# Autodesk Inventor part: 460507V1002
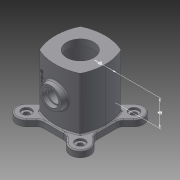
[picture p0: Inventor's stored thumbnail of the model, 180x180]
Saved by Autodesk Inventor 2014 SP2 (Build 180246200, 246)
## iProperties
Created: 2016-05
Part Number: 460507V1002
Material: Generic
Document SubType Name: Modeling
Designer: 달님반
Density: 1 g/cm^3
Appearance: Default
Author: 달님반
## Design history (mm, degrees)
sketch "스케치1"
  geometry: L1 (46, 0)-(46, -0.095); L2 (46, -46)-(-46, -46); L3 (-0.047, -0.047)-(66.486, -66.58); L4 (66.486, -66.58)-(-51.682, 51.587); L5 (-46, -46)-(46, 46); L6 (-46, -26.455)-(-46, 0); L7 (-46, 45.905)-(-46, 46); L8 (-0.095, 46)-(0, 46); A1 r 53 centre (-0.047, -0.047) between (-46, -26.455) and (-37.524, -37.524); A2 r 87.09 centre (41.09, -0.047) between (-37.524, 37.429) and (-37.524, -37.524); A3 r 86.222 centre (-0.047, -40.222) between (37.429, 37.429) and (-37.524, 37.429); A4 r 86.221 centre (-40.221, -0.047) between (37.429, -37.524) and (37.429, 37.429); A5 r 87.089 centre (-0.047, 41.089) between (-37.524, -37.524) and (37.429, -37.524); 1 further point
  constraints: 16 end point, 15 point on circle, 5 centre point, 5 point on line, 3 parallel, 2 perpendicular, 1 collinear, 1 horizontal, 1 horizontal alignment
  dimensions: "d1" = 106 diameter of A1; "d3" = 92 distance of L5.end L2.start; "d4" = 92 distance of L2.start L2.end
extrude "돌출1" new body sketch "스케치1" distance "d5" = 110; taper "d6" = 0 deg
sketch "스케치2" dims "d7" = 140
  geometry: L1 (-46, -0.095)-(-46, 0) reference; L2 (0, 46)-(0.095, 46) reference; L3 (0, 0)-(37.524, -37.524); L4 (59.177, -59.177)-(34.385, -34.385); L5 (62.225, -36.77)-(52.661, -27.205); L6 (36.77, -62.225)-(27.205, -52.661); L7 (-49, 49)-(49, 49); L8 (49, 49)-(49, -49); L9 (49, -49)-(-49, -49); L10 (-49, -49)-(-49, 49); C1 r 18 at (49.497, 49.497); C2 r 18 at (-49.497, 49.497); C3 r 18 at (-49.497, -49.497); A1 r 86.221 centre (40.221, -0.047) between (-37.429, 37.429) and (-46, 0) reference; A2 r 86.221 centre (40.221, -0.047) between (-46, -0.095) and (-37.429, -37.524) reference; A3 r 87.089 centre (0.047, 41.089) between (-37.429, -37.524) and (37.524, -37.524) reference; A4 r 87.09 centre (-41.09, -0.047) between (37.524, -37.524) and (37.524, 37.429) reference; A5 r 86.222 centre (0.047, -40.222) between (37.524, 37.429) and (0.095, 46) reference; A6 r 86.222 centre (0.047, -40.222) between (0, 46) and (-37.429, 37.429) reference; A7 r 18 centre (49.497, -49.497) between (62.225, -36.77) and (36.77, -62.225); A8 r 12.5 centre (61.5, -18.366) between (49, -18.366) and (52.661, -27.205); A9 r 12.5 centre (18.366, -61.5) between (27.205, -52.661) and (18.366, -49); 2 further points
  constraints: 16 end point, 6 centre point, 6 point on circle, 5 point on line, 4 parallel, 4 tangent, 1 coincident, 1 horizontal, 1 horizontal alignment, 1 midpoint, 1 perpendicular, 13 other
  dimensions: "d8" = 36 diameter of A7; "d11" = 360 deg dimension on L3.start A7.centre (derived); "d13" = 36 distance between parallel lines of L6 L5; "d14" = 98 distance of L7.start L7.end; "d15" = 98 distance of L7.end L8.end; "d16" = 25 diameter of A8; "d17" = 25 diameter of A9
extrude "돌출2" join sketch "스케치2" distance "d18" = 12; taper "d19" = 0 deg
sketch "스케치4"
  geometry: C1 r 25 at (0, 0); 1 further point
  constraints: 1 centre point, 1 coincident
  dimensions: "d20" = 50 diameter of C1
extrude "돌출3" cut sketch "스케치4" stored distance "d21" = 12; taper "d22" = 0 deg
sketch "스케치5"
  geometry: C1 r 35 at (0, 0); 1 further point
  constraints: 1 centre point, 1 coincident
  dimensions: "d24" = 70 diameter of C1
extrude "돌출4" cut sketch "스케치5" distance "d25" = 12; taper "d26" = 0 deg
sketch "스케치6"
  geometry: C1 r 35 at (0, 0); 1 further point
  constraints: 1 centre point, 1 coincident
  dimensions: "d27" = 70 diameter of C1
extrude "돌출5" cut sketch "스케치6" distance "d28" = 86; taper "d29" = 0 deg
sketch "스케치7"
  geometry: A1 r 18 centre (49.497, -49.497) between (36.77, -62.225) and (62.225, -36.77) reference; A2 r 18 centre (49.497, 49.497) between (62.225, 36.77) and (36.77, 62.225) reference; A3 r 18 centre (-49.497, 49.497) between (-36.77, 62.225) and (-62.225, 36.77) reference; A4 r 18 centre (-49.497, -49.497) between (-62.225, -36.77) and (-36.77, -62.225) reference; 1 further point
hole "구멍1" sketch "스케치7" at (-49.497, 49.497), (49.497, 49.497), (49.497, -49.497), (-49.497, -49.497) diameter "d33" = 10; stored, may be unused: countersink angle "d37" = 90 deg, drill point angle "d39" = 118 deg; dims "d34" = 6, "d35" = 18, "d36" = 4, "d38" = 8
node "작업 평면1"
sketch "스케치8"
  geometry: L1 (-18.414, 12)-(18.319, 12) reference; C1 r 20 at (-0.047, 61); 1 further point
  constraints: 1 centre point
  dimensions: "d40" = 40 diameter of C1; "d41" = 49 distance from line of C1.centre L1
node "작업 평면2"
fillet "모깎기1" dims "d51" = 2
fillet "모깎기2" dims "d52" = 2
node "작업 평면3"
sketch "스케치12"
  geometry: L1 (-34.953, 12)-(35.047, 12) reference; C1 r 20 at (0.047, 61); 1 further point
  constraints: 1 centre point
  dimensions: "d54" = 40 diameter of C1; "d55" = 49 distance from line of C1.centre L1
node "작업 평면4"
node "작업 평면5"
sketch "스케치13"
  geometry: C1 r 20 at (0, 61) reference; 1 further point
extrude "돌출9" join sketch "스케치13" stored distance "d58" = 20; taper "d59" = 10 deg
sketch "스케치14"
  geometry: C1 r 20 at (0, 0) reference; C2 r 15 at (0, 0); 1 further point
  constraints: 1 centre point, 1 coincident
  dimensions: "d60" = 30 diameter of C2
extrude "돌출10" cut sketch "스케치14" distance "d61" = 8; taper "d62" = 0 deg
sketch "스케치15"
  geometry: C1 r 15 at (0, 0) reference; C2 r 12.5 at (0, 0); 1 further point
  constraints: 1 centre point, 1 coincident
  dimensions: "d63" = 25 diameter of C2
extrude "돌출11" cut sketch "스케치15" distance "d64" = 20; taper "d65" = 0 deg
fillet "모깎기4" dims "d66" = 3
fillet "모깎기5" dims "d67" = 3
sketch "스케치16"
  geometry: C1 r 25 at (0, 0) reference; C2 r 25 at (0, 0)
  constraints: 1 centre point, 1 coincident, 1 concentric
extrude "돌출12" cut sketch "스케치16" stored distance "d68" = 20; taper "d69" = 0 deg
fillet "모깎기6" dims "d70" = 3
node "작업 평면7"
  node "작업 평면6"
sketch "스케치18"
  geometry: L1 (42.481, 110)-(-29.373, 110) reference; 2 further points
  constraints: 1 other
  dimensions: "d73" = 49 distance from line of point (-22.312, 61) L1
feature "엠보싱1" sketch "스케치18" dims "d1" = 106, "d3" = 92, "d4" = 92, "d74" = 0.5, "d75" = 0
node "솔리드1"
pattern_circular "원형 패턴1" dims angle "d31" = 360 deg
other parameters: "d42" = 55, "d56" = 55, "d57" = -55, "d71" = -10 deg, "d72" = -65.75
